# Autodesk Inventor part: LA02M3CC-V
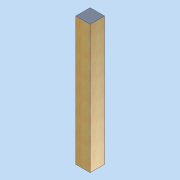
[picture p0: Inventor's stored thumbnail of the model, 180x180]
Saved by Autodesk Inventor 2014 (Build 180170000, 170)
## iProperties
Created: 2011-04
Part Number: LA02M3CC-V
Document SubType Name: Modeling
Designer: david.appleford
Density: 0.398379 g/cm^3
Description: Lug Middle 0.5w 3 Slots
Cost Center: £6.00
Mass: 1120 g
Surface Area: 1746.24 cm^2
Volume: 2811.39 cm^3
Material: 000 Redwood
Appearance: Wood (Pine)
Justset: False
Author: david.appleford
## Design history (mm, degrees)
sketch "Sketch1"
  geometry: L1 (0, 0)-(68, 0); L2 (68, 0)-(68, 68); L3 (68, 68)-(0, 68); L4 (0, 68)-(0, 0)
  constraints: 8 end point, 2 parallel, 1 horizontal, 1 perpendicular
  dimensions: "d0" = 68 distance between parallel lines of L2 L4 (= t); "d1" = 68 distance between parallel lines of L1 L3 (= t)
extrude "Extrusion1" new body sketch "Sketch1" distance "d2" = 608 (= 0.5 x w - Cl); taper "d3" = 0 deg
body "Solid1"
other parameters: "t" = 68 [user parameter; used in 2 equation terms], "Cl" = 2 [user parameter; used in 1 equation term]
